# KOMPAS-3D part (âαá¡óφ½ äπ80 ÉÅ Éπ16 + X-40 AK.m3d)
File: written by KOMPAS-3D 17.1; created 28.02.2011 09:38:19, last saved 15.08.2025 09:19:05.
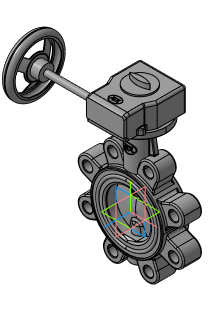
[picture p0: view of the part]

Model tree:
1. Плоскость XY
2. Плоскость ZX
3. Плоскость ZY
4. Ось X
5. Ось Y
6. Ось Z
7. Начало координат
8. Операция без истории:5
